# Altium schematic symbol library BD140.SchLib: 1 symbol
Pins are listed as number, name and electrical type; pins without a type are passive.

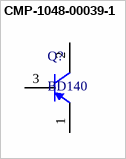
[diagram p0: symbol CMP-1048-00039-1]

## CMP-1048-00039-1
designator Q?, comment BD140
Plastic Medium-Power Silicon PNP Transistor, 3-Pin TO-225, Bulk Box; Manufacturer: On Semiconductor; IC Continuous (A): 1.5
footprint ONSC-TO-225-3-77-09 (FM, 3-Leads, Body 7.8x3mm, Pitch 2.29mm)
pins: 1 E, 2 C, 3 B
